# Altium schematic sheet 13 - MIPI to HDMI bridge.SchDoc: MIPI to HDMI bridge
size A3; PageSetup: Record=PageOptions¦CenterHorizontal=True¦CenterVertical=True¦PrintScale=0.70¦XCorrection=1.00¦YCorrection=1.00¦PrintKind=0¦BorderSize=5000000¦LeftOffset=0¦BottomOffset=0¦Orientation=2¦PaperLength=4200¦PaperWidth=2970¦Scale=100¦PaperSource=7¦PrintQuality=600¦MediaType=1¦DitherType=10¦PaperKind=A4¦PrintScaleMode=1; Author: Juan Anzola; SheetNumber: 13; SheetTotal: 21
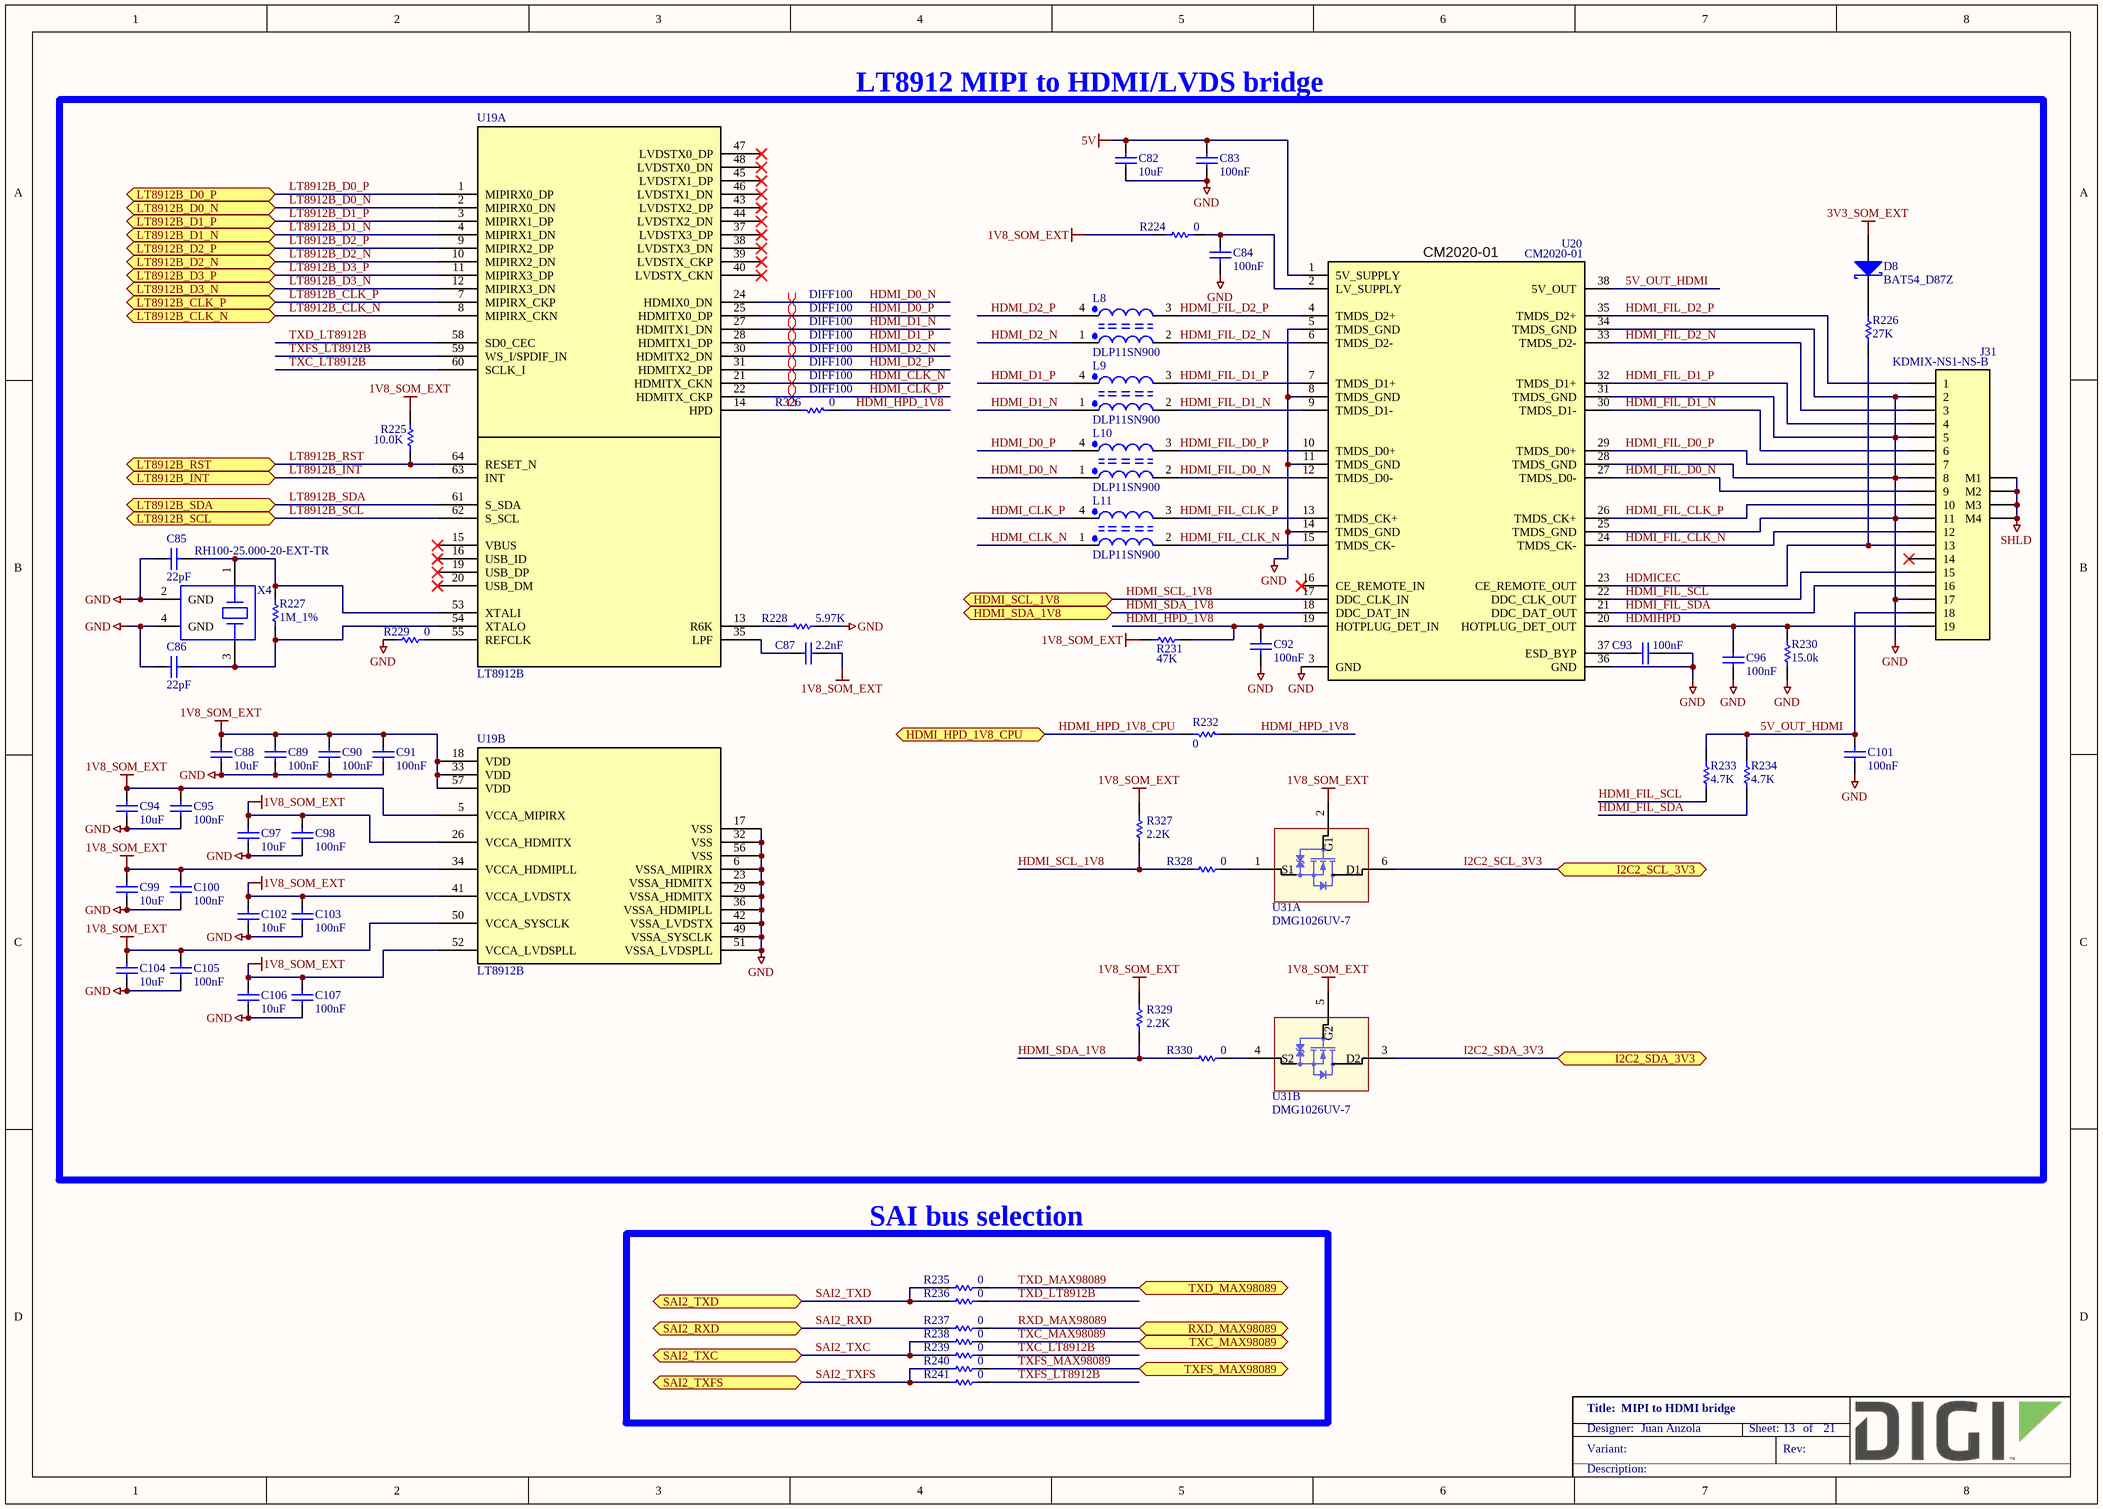
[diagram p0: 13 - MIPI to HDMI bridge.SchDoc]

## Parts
C82  10uF  [CAPC1005X55N]
C83  100nF  [CAPC1005X55N]
C84  100nF  [CAPC1005X55N]
C85  22pF  [CAPC1005X55N]
C86  22pF  [CAPC1005X55N]
C87  2.2nF  [CAPC1608X90N]
C88  10uF  [CAPC1005X55N]
C89  100nF  [CAPC1005X55N]
C90  100nF  [CAPC1005X55N]
C91  100nF  [CAPC1005X55N]
C92  100nF  [CAPC1005X55N]
C93  100nF  [CAPC1005X55N]
C94  10uF  [CAPC1005X55N]
C95  100nF  [CAPC1005X55N]
C96  100nF  [CAPC1005X55N]
C97  10uF  [CAPC1005X55N]
C98  100nF  [CAPC1005X55N]
C99  10uF  [CAPC1005X55N]
C100  100nF  [CAPC1005X55N]
C101  100nF  [CAPC1005X55N]
C102  10uF  [CAPC1005X55N]
C103  100nF  [CAPC1005X55N]
C104  10uF  [CAPC1005X55N]
C105  100nF  [CAPC1005X55N]
C106  10uF  [CAPC1005X55N]
C107  100nF  [CAPC1005X55N]
D8  BAT54_D87Z  [SOT95P240X110_AXK-3N]
J31  KDMIX-NS1-NS-B  [KYCON_KDMIX]
L8  DLP11SN900  [FIL_DLP11S]
L9  DLP11SN900  [FIL_DLP11S]
L10  DLP11SN900  [FIL_DLP11S]
L11  DLP11SN900  [FIL_DLP11S]
R224  0  [RESC1005X40N]
R225  10.0K  [RESC1005X40N]
R226  27K  [RESC1005X40N]
R227  1M_1%  [RESC1005X40N]
R228  5.97K  [RESC1005X40N]
R229  0  [RESC1005X40N]
R230  15.0k  [RESC1005X40N]
R231  47K  [RESC1005X40N]
R232  0  [RESC1005X40N]
R233  4.7K  [RESC1005X40N]
R234  4.7K  [RESC1005X40N]
R235  0  [RESC1609X55N]
R236  0  [RESC1609X55N]
R237  0  [RESC1609X55N]
R238  0  [RESC1609X55N]
R239  0  [RESC1609X55N]
R240  0  [RESC1609X55N]
R241  0  [RESC1609X55N]
R326  0  [RESC1005X40N]
R327  2.2K  [RESC1005X40N]
R328  0  [RESC1005X40N]
R329  2.2K  [RESC1005X40N]
R330  0  [RESC1005X40N]
U19  LT8912B  [QFN40P750X750X80-64N]  (parts A,B of 2)
U20  CM2020-01  [SOP50P640X120-38N]
U31  DMG1026UV-7  [SOTFL50P160X60-6N]  (parts A,B of 2)
X4  RH100-25.000-20-EXT-TR  [OSC210P320X250X90-4N]

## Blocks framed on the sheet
LT8912 MIPI to HDMI/LVDS bridge: C82-C107 D8 J31 L8-L11 R224-R234 R326-R330 U19 U20 U31 X4
SAI bus selection: R235-R241

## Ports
HDMI_HPD_1V8_CPU (bidir), HDMI_SCL_1V8 (bidir), HDMI_SDA_1V8 (bidir), I2C2_SCL_3V3 (bidir), I2C2_SDA_3V3 (bidir), LT8912B_CLK_N (bidir), LT8912B_CLK_P (bidir), LT8912B_D0_N (bidir), LT8912B_D0_P (bidir), LT8912B_D1_N (bidir), LT8912B_D1_P (bidir), LT8912B_D2_N (bidir), LT8912B_D2_P (bidir), LT8912B_D3_N (bidir), LT8912B_D3_P (bidir), LT8912B_INT (bidir), LT8912B_RST (bidir), LT8912B_SCL (bidir), LT8912B_SDA (bidir), RXD_MAX98089 (bidir), SAI2_RXD (bidir), SAI2_TXC (bidir), SAI2_TXD (bidir), SAI2_TXFS (bidir), TXC_MAX98089 (bidir), TXD_MAX98089 (bidir), TXFS_MAX98089 (bidir)

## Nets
1V8_SOM_EXT: C87.2 C88.2 C89.2 C90.2 C91.2 C94.2 C95.2 C97.2 C98.2 C99.2 C100.2 C102.2 C103.2 C104.2 C105.2 C106.2 C107.2 R224.2 R225.1 R231.1 R327.2 R329.2 U19.5(VCCA_MIPIRX) U19.18(VDD) U19.26(VCCA_HDMITX) U19.33(VDD) U19.34(VCCA_HDMIPLL) U19.41(VCCA_LVDSTX) U19.50(VCCA_SYSCLK) U19.52(VCCA_LVDSPLL) U19.57(VDD) U31.2(G1) U31.5(G2)
3V3_SOM_EXT: D8.A
5V: C82.2 C83.2 U20.1(5V_SUPPLY)
GND: C82.1 C83.1 C84.1 C85.1 C86.1 C88.1 C89.1 C90.1 C91.1 C92.1 C93.1 C94.1 C95.1 C96.1 C97.1 C98.1 C99.1 C100.1 C101.1 C102.1 C103.1 C104.1 C105.1 C106.1 C107.1 J31.2 J31.5 J31.8 J31.11 J31.17 R228.2 R229.1 R230.1 U19.6(VSSA_MIPIRX) U19.17(VSS) U19.23(VSSA_HDMITX) U19.29(VSSA_HDMITX) U19.32(VSS) U19.36(VSSA_HDMIPLL) U19.42(VSSA_LVDSTX) U19.49(VSSA_SYSCLK) U19.51(VSSA_LVDSPLL) U19.56(VSS) U20.3(GND) U20.5(TMDS_GND) U20.8(TMDS_GND) U20.11(TMDS_GND) U20.14(TMDS_GND) U20.25(TMDS_GND) U20.28(TMDS_GND) U20.31(TMDS_GND) U20.34(TMDS_GND) U20.36(GND) X4.2(GND) X4.4(GND)
SHLD: J31.M1 J31.M2 J31.M3 J31.M4
5V_OUT_HDMI: C101.2 J31.18 R233.1 R234.1 U20.38(5V_OUT)
HDMI_CLK_N: L11.1 U19.21(HDMITX_CKN)
HDMI_CLK_P: L11.4 U19.22(HDMITX_CKP)
HDMI_D0_N: L10.1 U19.24(HDMIX0_DN)
HDMI_D0_P: L10.4 U19.25(HDMITX0_DP)
HDMI_D1_N: L9.1 U19.27(HDMITX1_DN)
HDMI_D1_P: L9.4 U19.28(HDMITX1_DP)
HDMI_D2_N: L8.1 U19.30(HDMITX2_DN)
HDMI_D2_P: L8.4 U19.31(HDMITX2_DP)
HDMI_FIL_CLK_N: J31.12 L11.2 U20.15(TMDS_CK-) U20.24(TMDS_CK-)
HDMI_FIL_CLK_P: J31.10 L11.3 U20.13(TMDS_CK+) U20.26(TMDS_CK+)
HDMI_FIL_D0_N: J31.9 L10.2 U20.12(TMDS_D0-) U20.27(TMDS_D0-)
HDMI_FIL_D0_P: J31.7 L10.3 U20.10(TMDS_D0+) U20.29(TMDS_D0+)
HDMI_FIL_D1_N: J31.6 L9.2 U20.9(TMDS_D1-) U20.30(TMDS_D1-)
HDMI_FIL_D1_P: J31.4 L9.3 U20.7(TMDS_D1+) U20.32(TMDS_D1+)
HDMI_FIL_D2_N: J31.3 L8.2 U20.6(TMDS_D2-) U20.33(TMDS_D2-)
HDMI_FIL_D2_P: J31.1 L8.3 U20.4(TMDS_D2+) U20.35(TMDS_D2+)
HDMI_FIL_SCL: J31.15 R233.2 U20.22(DDC_CLK_OUT)
HDMI_FIL_SDA: J31.16 R234.2 U20.21(DDC_DAT_OUT)
HDMI_HPD_1V8: C92.2 R231.2 R232.1 R326.1 U20.19(HOTPLUG_DET_IN)
HDMI_HPD_1V8_CPU: R232.2 ; port HDMI_HPD_1V8_CPU
HDMI_SCL_1V8: R327.1 R328.1 U20.17(DDC_CLK_IN) ; port HDMI_SCL_1V8
HDMI_SDA_1V8: R329.1 R330.1 U20.18(DDC_DAT_IN) ; port HDMI_SDA_1V8
HDMICEC: J31.13 R226.2 U20.23(CE_REMOTE_OUT)
HDMIHPD: C96.2 J31.19 R230.2 U20.20(HOTPLUG_DET_OUT)
I2C2_SCL_3V3: U31.6(D1) ; port I2C2_SCL_3V3
I2C2_SDA_3V3: U31.3(D2) ; port I2C2_SDA_3V3
LT8912B_CLK_N: U19.8(MIPIRX_CKN) ; port LT8912B_CLK_N
LT8912B_CLK_P: U19.7(MIPIRX_CKP) ; port LT8912B_CLK_P
LT8912B_D0_N: U19.2(MIPIRX0_DN) ; port LT8912B_D0_N
LT8912B_D0_P: U19.1(MIPIRX0_DP) ; port LT8912B_D0_P
LT8912B_D1_N: U19.4(MIPIRX1_DN) ; port LT8912B_D1_N
LT8912B_D1_P: U19.3(MIPIRX1_DP) ; port LT8912B_D1_P
LT8912B_D2_N: U19.10(MIPIRX2_DN) ; port LT8912B_D2_N
LT8912B_D2_P: U19.9(MIPIRX2_DP) ; port LT8912B_D2_P
LT8912B_D3_N: U19.12(MIPIRX3_DN) ; port LT8912B_D3_N
LT8912B_D3_P: U19.11(MIPIRX3_DP) ; port LT8912B_D3_P
LT8912B_INT: U19.63(INT) ; port LT8912B_INT
LT8912B_RST: R225.2 U19.64(RESET_N) ; port LT8912B_RST
LT8912B_SCL: U19.62(S_SCL) ; port LT8912B_SCL
LT8912B_SDA: U19.61(S_SDA) ; port LT8912B_SDA
RXD_MAX98089: R237.2 ; port RXD_MAX98089
SAI2_RXD: R237.1 ; port SAI2_RXD
SAI2_TXC: R238.1 R239.1 ; port SAI2_TXC
SAI2_TXD: R235.1 R236.1 ; port SAI2_TXD
SAI2_TXFS: R240.1 R241.1 ; port SAI2_TXFS
TXC_LT8912B: R239.2 U19.60(SCLK_I)
TXC_MAX98089: R238.2 ; port TXC_MAX98089
TXD_LT8912B: R236.2 U19.58(SD0_CEC)
TXD_MAX98089: R235.2 ; port TXD_MAX98089
TXFS_LT8912B: R241.2 U19.59(WS_I/SPDIF_IN)
TXFS_MAX98089: R240.2 ; port TXFS_MAX98089
NetC84_2: C84.2 R224.1 U20.2(LV_SUPPLY)
NetC85_2: C85.2 R227.2 U19.53(XTALI) X4.1
NetC86_2: C86.2 R227.1 U19.54(XTALO) X4.3
NetC87_1: C87.1 U19.35(LPF)
NetC93_2: C93.2 U20.37(ESD_BYP)
NetD8_K: D8.K R226.1
NetR228_1: R228.1 U19.13(R6K)
NetR229_2: R229.2 U19.55(REFCLK)
NetR326_2: R326.2 U19.14(HPD)
NetR328_2: R328.2 U31.1(S1)
NetR330_2: R330.2 U31.4(S2)

Not connected (* = marked no-connect by the designer): J31 14*; U19 15(VBUS)* 16(USB_ID)* 19(USB_DP)* 20(USB_DM)* 37(LVDSTX3_DP)* 38(LVDSTX3_DN)* 39(LVDSTX_CKP)* 40(LVDSTX_CKN)* 43(LVDSTX2_DP)* 44(LVDSTX2_DN)* 45(LVDSTX1_DP)* 46(LVDSTX1_DN)* 47(LVDSTX0_DP)* 48(LVDSTX0_DN)*; U20 16(CE_REMOTE_IN)*

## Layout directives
differential pair; net class DIFF100: HDMI_CLK_N, HDMI_CLK_P, HDMI_D0_N, HDMI_D0_P, HDMI_D1_N, HDMI_D1_P, HDMI_D2_N, HDMI_D2_P

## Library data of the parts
C82 C88 C94 C97 C99 C102 C104 C106 = 1001168: CAP CER 10UF 10V 20% X5R 0402; Part_Type: Capacitor; Manufacturer: Samsung; Manufacturer_Part_Number: CL05A106MP5NUNC; Digi_PN: 14050689; Component_Life_Cycle_State: Reviewed; Area: 0.95; Project: CCWMX6_SBC board
C83 C84 C89-C93 C95 C96 C98 C100 C101 C103 C105 C107 = 1000006: CAP 100nF 16V 10% X7R 0402; Part_Type: Capacitor; Manufacturer: Murata; Manufacturer_Part_Number: GRM155R71C104KA88D; Component_Life_Cycle_State: CAD Reviewed; Area: 0.95; Project: KITT; Tolerance: 10; Digi_PN: 14050552
C85 C86 = 1001166: CAP CER 22PF 50V 5% NP0 0402; Part_Type: Capacitor; Manufacturer: Murata; Manufacturer_Part_Number: GRM1555C1H220JA01D; Note: 14050749 = Digi No. for GE WDNU; Digi_PN: 14050367; Component_Life_Cycle_State: Reviewed; Area: 0,95; Project: CCWMX6_SBC board; Temp_Coef: C0G, NP0
C87 = 1002727: CAP CER 2200PF 50V X7R 5% 0603; Part_Type: Capacitor; Manufacturer: Kemet; Manufacturer_Part_Number: C0603C222J5RACTU; Digi_PN: 14050443; Component_Life_Cycle_State: Pending; Area: 2,27
D8 = 1001169: DIODE SCHOTTKY 30V 0.2A SOT23-3; Part_Type: IC; Manufacturer: Fairchild Semiconductor; Digi_PN: 17050507; Component_Life_Cycle_State: Reviewed; Area: 8; Project: CCWMX6_SBC board
J31 = 1001123: HDMI RECEPTACLE, SMT; Part_Type: Connector; Manufacturer: KYCON; Digi_PN: 18000451; Component_Life_Cycle_State: Reviewed; Area: 174; Project: CCWMX6_SBC board
L8-L11 = 1001014: CHOKE COIL COMMON MODE 150MA SMD; Part_Type: Inductor; Manufacturer: Murata; Manufacturer_Part_Number: DLP11SN900HL2L; Component_Life_Cycle_State: Reviewed; Area: 3.94; Project: ResMed RF Test Interface Board; Digi_PN: 21000531
R224 R229 R232 R326 = 1000076: RES 0.0 OHM 1/10W 0402 SMD; Part_Type: Resistor; Manufacturer: Panasonic - ECG; Manufacturer_Part_Number: ERJ-2GE0R00X; Digi_PN: 13050387; Component_Life_Cycle_State: Proven; Area: 0,95; Project: Adjustable Foundation; Power_WV_SRF: 10
R225 = 1000537: RES 10.0K OHM 1/10W 1% 0402 SMD; Part_Type: Resistor; Manufacturer: Panasonic - ECG; Manufacturer_Part_Number: ERJ-2RKF1002X; Component_Life_Cycle_State: CAD Reviewed; Area: 0.95; Project: KITT; Power_WV_SRF: 100; Digi_PN: 13051084
R226 = 1001153: RES 27.0K OHM 1/16W 1% 0402 SMD; Part_Type: Resistor; Manufacturer: Yageo; Manufacturer_Part_Number: RC0402FR-0727KL; Digi_PN: 13050609; Component_Life_Cycle_State: Reviewed; Area: 0.95; Project: CCWMX6_SBC board
R227 = 1000971: RES 1.00M OHM 1/16W 1% 0402 SMD; Part_Type: Resistor; Manufacturer: Yageo; Manufacturer_Part_Number: RC0402FR-071ML; Note: 13051098 = Digi No. for GE WDNU; Digi_PN: 13050561; Component_Life_Cycle_State: Reviewed; Area: 0,95; Power_WV_SRF: 63; Tolerance: 1
R228 = 1002748: RES 5.97K OHM 0.1% 1/10W 0402; Part_Type: Resistor; Manufacturer: Vishay Dale; Manufacturer_Part_Number: TNPW04025K97BEED; Digi_PN: 13000099; Component_Life_Cycle_State: Created; Area: 0,95
R230 = 1000174: RES 15.0K OHM 1/10W 1% 0402 SMD; Part_Type: Resistor; Manufacturer: Panasonic - ECG; Manufacturer_Part_Number: ERJ-2RKF1502X; Component_Life_Cycle_State: CAD Reviewed; Area: 0.95; Project: KITT; Power_WV_SRF: 10; Digi_PN: 13050446
R231 = 1001155: RES 47.0K OHM 1/16W 1% 0402 SMD; Part_Type: Resistor; Manufacturer: Vishay Dale; Manufacturer_Part_Number: CRCW040247K0FKED; Digi_PN: 13050646; Component_Life_Cycle_State: Reviewed; Area: 0.95; Project: CCWMX6_SBC board
R233 R234 = 1000038: RES 4.7K OHM 1/10W 5% 0402 SMD; Part_Type: Resistor; Manufacturer: Panasonic - ECG; Manufacturer_Part_Number: ERJ-2GEJ472X; Component_Life_Cycle_State: Proven; Area: 0.95; Project: Adjustable Foundation; Power_WV_SRF: 100; Tolerance: 5; Digi_PN: 13050549
R235-R241 = 1000208: RES 0.0 OHM 1/10W 0603; Part_Type: Resistor; Manufacturer: Panasonic - ECG; Manufacturer_Part_Number: ERJ-3GEY0R00V; Note: 13051103 = Digi No. for GE WDNU; Digi_PN: 13050568; Component_Life_Cycle_State: Reviewed; Area: 2,5; Voltage: 75V
R327 R329 = 1001156: RES 2.20K OHM 1/16W 1% 0402 SMD; Part_Type: Resistor; Manufacturer: Yageo; Manufacturer_Part_Number: RC0402FR-072K2L; Digi_PN: 13050699; Component_Life_Cycle_State: Reviewed; Area: 0.95; Project: CCWMX6_SBC board; Note: 13051099 = Digi No. for GE WDNU
R328 R330 = 1000076: RES 0.0 OHM 1/10W 0402 SMD; Part_Type: Resistor; Manufacturer: Panasonic - ECG; Manufacturer_Part_Number: ERJ-2GE0R00X; Component_Life_Cycle_State: Proven; Area: 0.95; Project: Adjustable Foundation; Power_WV_SRF: 10; Digi_PN: 13050387
U19 = 1002722: MIPI DSI BRIDGE TO LVDS/HDMI SINGLE CHANNEL; Part_Type: IC; Manufacturer: Lontium Semiconductor; Digi_PN: 16000199; Component_Life_Cycle_State: Pending; Area: 76,04
U20 = 1001125: IC HDMI XMITTER PORT P/I 38TSSOP; Manufacturer: On Semiconductor; Digi_PN: 16051861; Component_Life_Cycle_State: Reviewed; Area: 43; Project: CCWMX6_SBC board
U31 = 1001009: MOSFET DL N-CH 60V 410MA SOT-563; Part_Type: Transistor; Manufacturer: Diodes, Inc.; Digi_PN: 17050796; Component_Life_Cycle_State: Reviewed; Area: 2,89; Project: ConnectCore i.MX6 module
X4 = 1001497: SMCRY,25MHZ 50PPM 20PF RH100 EXT; Part_Type: Crystals-Oscillators; Manufacturer: Raltron; Digi_PN: 20000285; Component_Life_Cycle_State: Reviewed; Area: 3,2; Project: CCWMX6_SBC board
